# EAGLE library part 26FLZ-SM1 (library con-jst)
CONNECTOR
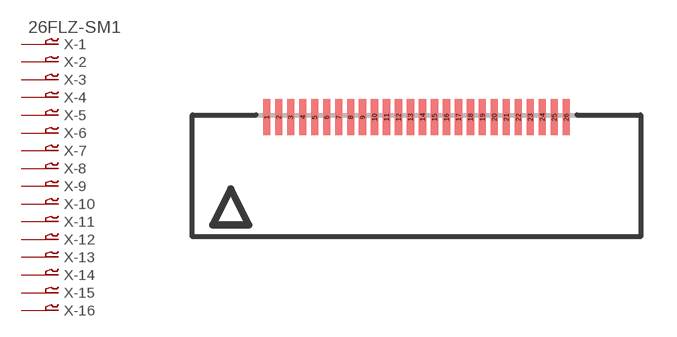
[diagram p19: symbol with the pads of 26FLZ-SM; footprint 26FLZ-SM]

Designator prefix X; gates -1=P-VN -2=P-N -3=P-N -4=P-N -5=P-N -6=P-N -7=P-N -8=P-N -9=P-N -10=P-N -11=P-N -12=P-N -13=P-N -14=P-N -15=P-N -16=P-N -17=P-N -18=P-N -19=P-N -20=P-N -21=P-N -22=P-N -23=P-N -24=P-N -25=P-N -26=P-N

## 26FLZ-SM1 (OC_FARNELL: unknown; OC_NEWARK: unknown)  [26FLZ-SM]
1  -1:1  pas
2  -2:1  pas
3  -3:1  pas
4  -4:1  pas
5  -5:1  pas
6  -6:1  pas
7  -7:1  pas
8  -8:1  pas
9  -9:1  pas
10  -10:1  pas
11  -11:1  pas
12  -12:1  pas
13  -13:1  pas
14  -14:1  pas
15  -15:1  pas
16  -16:1  pas
17  -17:1  pas
18  -18:1  pas
19  -19:1  pas
20  -20:1  pas
21  -21:1  pas
22  -22:1  pas
23  -23:1  pas
24  -24:1  pas
25  -25:1  pas
26  -26:1  pas

## Footprint 26FLZ-SM (pad centres in mm)
CONNECTOR
smd 0.3 x 1.5: 1 -6.25,2.5; 2 -5.75,2.5; 3 -5.25,2.5; 4 -4.75,2.5; 5 -4.25,2.5; 6 -3.75,2.5; 7 -3.25,2.5; 8 -2.75,2.5; 9 -2.25,2.5; 10 -1.75,2.5; 11 -1.25,2.5; 12 -0.75,2.5; 13 -0.25,2.5; 14 0.25,2.5; 15 0.75,2.5; 16 1.25,2.5; 17 1.75,2.5; 18 2.25,2.5; 19 2.75,2.5; 20 3.25,2.5; 21 3.75,2.5; 22 4.25,2.5; 23 4.75,2.5; 24 5.25,2.5; 25 5.75,2.5; 26 6.25,2.5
